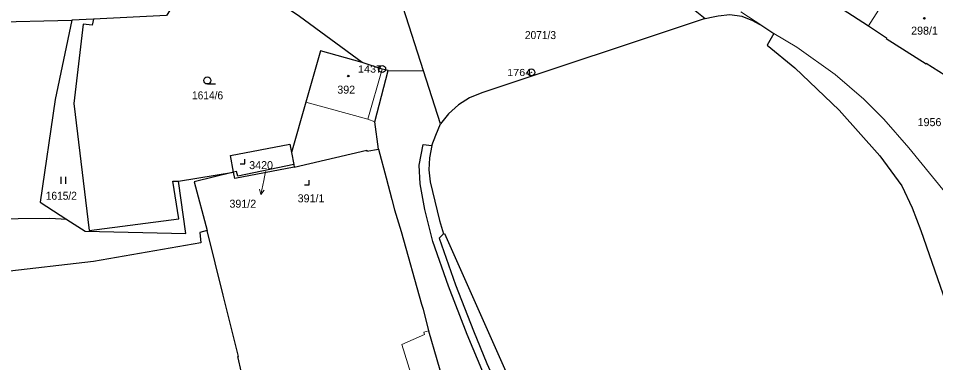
# Model space of a CAD drawing. Extents: x -679733 to -673243, y -1075091 to -1066557.
# Drawn here: x -676852.3 to -676657.5, y -1071521.5 to -1071448.4 of the extents above; entities that cross this region are included whole.
import ezdxf
from ezdxf.enums import TextEntityAlignment as Align

# ---------------------------------------------------------------- set-up
doc = ezdxf.new("R2010")
doc.units = 0
doc.header["$LTSCALE"] = 0.68
for name, color, linetype, lineweight in [('1', 7, 'Continuous', 25), ('3', 7, 'Continuous', 25), ('4', 7, 'Continuous', 13), ('5', 7, 'Continuous', 25), ('7', 7, 'Continuous', 13), ('8', 7, 'Continuous', 25)]:
    doc.layers.add(name, color=color, linetype=linetype, lineweight=lineweight)
doc.layers.add('2', color=7, linetype='Continuous')

msp = doc.modelspace()

# ---------------------------------------------------------------- linework, layer by layer
at = {"layer": '1'}
for p, q in [((-676836.4, -1071448.49), (-676841, -1071448.71)), ((-676773.77, -1071459.42), (-676766.29, -1071459.51))]:
    msp.add_line(p, q, dxfattribs=at)
for points in [[(-676708.35, -1071426.89), (-676710.19, -1071425.7), (-676715.7, -1071440.94), (-676706.46, -1071448.39)], [(-676813.29, -1071435.89), (-676820.87, -1071447.75), (-676836.4, -1071448.49)], [(-676779.29, -1071457.75), (-676792.63, -1071447.96), (-676797.15, -1071444.93), (-676806.53, -1071439.04), (-676813.29, -1071435.89)], [(-676683.31, -1071443.03), (-676678.47, -1071446), (-676678.32, -1071445.78), (-676677.41, -1071446.35), (-676671.78, -1071449.97), (-676667.98, -1071452.47), (-676668.07, -1071452.62), (-676659.58, -1071457.99), (-676659.52, -1071457.9), (-676655.53, -1071460.4), (-676642.15, -1071468.89)], [(-676766.29, -1071459.51), (-676770.64, -1071446.07), (-676770.3, -1071445.35)], [(-676957.85, -1071463.57), (-676942.22, -1071453.22), (-676935.48, -1071451.38), (-676927.1, -1071450.58), (-676915.56, -1071448.55), (-676905.18, -1071446.9), (-676895.66, -1071447), (-676891.77, -1071447.7), (-676885.75, -1071448.33), (-676876.83, -1071449.08), (-676869.56, -1071449.42), (-676858.82, -1071449.13), (-676841, -1071448.71)], [(-676706.46, -1071448.39), (-676704.76, -1071448.03), (-676703.73, -1071447.81), (-676701.26, -1071447.54), (-676698.72, -1071447.92), (-676696.46, -1071448.78), (-676694.26, -1071449.98), (-676691.89, -1071451.57), (-676693.28, -1071454.07), (-676687.45, -1071458.85), (-676678.05, -1071467.82), (-676669.42, -1071477.57), (-676664.74, -1071483.89), (-676662.51, -1071488.58), (-676660.71, -1071493.4), (-676651.25, -1071520.53)], [(-676841, -1071448.71), (-676844.52, -1071465.57), (-676847.69, -1071487.35), (-676842.01, -1071491.03)], [(-676836.4, -1071448.49), (-676836.62, -1071449.77), (-676838.6, -1071449.62), (-676840.54, -1071466.42), (-676837.3, -1071493.41), (-676818.28, -1071490.9), (-676819.52, -1071482.92), (-676818.29, -1071482.89), (-676806.65, -1071481)], [(-676706.46, -1071448.39), (-676753.93, -1071464.16), (-676756.51, -1071465.26), (-676758.86, -1071466.72), (-676760.97, -1071468.64), (-676762.66, -1071470.73)], [(-676779.29, -1071457.75), (-676788.15, -1071455.25), (-676791.29, -1071466.12), (-676794.31, -1071476.87), (-676793.84, -1071479.38), (-676793.73, -1071479.96)], [(-676773.77, -1071459.42), (-676775.08, -1071459.11), (-676779.29, -1071457.75)], [(-676775.85, -1071476.13), (-676776.64, -1071470.3), (-676773.77, -1071459.42)], [(-676764.54, -1071475.38), (-676763.69, -1071473.15), (-676762.66, -1071470.73), (-676766.29, -1071459.51)], [(-676806.65, -1071481), (-676807.31, -1071477.46), (-676794.65, -1071475.1), (-676794.31, -1071476.87)], [(-676753.54, -1071523.73), (-676757.03, -1071515.47), (-676760.96, -1071505.19), (-676764.28, -1071495.76), (-676766.04, -1071488.95), (-676767.03, -1071483.49), (-676767.2, -1071479.54), (-676766.39, -1071475.11), (-676764.54, -1071475.38)], [(-676793.73, -1071479.96), (-676778.34, -1071476.35), (-676778.3, -1071476.55), (-676775.85, -1071476.13)], [(-676775.85, -1071476.13), (-676774.25, -1071482.22), (-676773, -1071486.82), (-676772.46, -1071488.98), (-676771.07, -1071493.58), (-676766.7, -1071509.07), (-676766.37, -1071510.09), (-676765.26, -1071514.71), (-676761.72, -1071526.9), (-676760.25, -1071531.41), (-676759.56, -1071533.91), (-676756.1, -1071546.01)], [(-676764.54, -1071475.38), (-676765.03, -1071477.96), (-676765.17, -1071480.52), (-676764.91, -1071483.06), (-676762.89, -1071491.26), (-676762.03, -1071494.13)], [(-676806.65, -1071481), (-676815.01, -1071483.07), (-676812.2, -1071493.43)], [(-676793.84, -1071479.38), (-676805.72, -1071481.85), (-676805.99, -1071480.9), (-676806.65, -1071481)], [(-676793.73, -1071479.96), (-676806.39, -1071482.37), (-676806.65, -1071481)], [(-676842.01, -1071491.03), (-676838.11, -1071493.55), (-676816.77, -1071494.03), (-676818.29, -1071482.89)], [(-676842.01, -1071491.03), (-676845.64, -1071490.85), (-676865.79, -1071491.03), (-676869.03, -1071491.11), (-676888.24, -1071491.34), (-676898.16, -1071492.99), (-676910.53, -1071491.92), (-676915.98, -1071492.56), (-676921.53, -1071495.81), (-676926.39, -1071499.92), (-676929.35, -1071501.56), (-676945.58, -1071505.99), (-676961.23, -1071514.08), (-676969.66, -1071515.7), (-676981.66, -1071516.36), (-676989.83, -1071513.04), (-676992.52, -1071510.05), (-676993.5, -1071508.1), (-676992.89, -1071505.67), (-676991.53, -1071503.51), (-676987.74, -1071501.24), (-676980.5, -1071498.63), (-676974.34, -1071494.41)], [(-676812.2, -1071493.43), (-676813.76, -1071493.82), (-676813.57, -1071496.03), (-676836.38, -1071500.01), (-676855.98, -1071502.22), (-676871.03, -1071503.58), (-676888.75, -1071507.78), (-676905.07, -1071511.48), (-676917.72, -1071513.49), (-676933.11, -1071515.38), (-676941.77, -1071519.32), (-676931.84, -1071554.09), (-676916.35, -1071551.78)], [(-676804.95, -1071523.55), (-676805.72, -1071520.17), (-676805.55, -1071520.12), (-676808.81, -1071507.1), (-676812.2, -1071493.43)], [(-676762.03, -1071494.13), (-676762.94, -1071495.05), (-676759.5, -1071504.94), (-676755.7, -1071514.74), (-676752.84, -1071521.62), (-676750.39, -1071527.09), (-676748.58, -1071527.96), (-676747.78, -1071528.25), (-676742.3, -1071540.02), (-676742.65, -1071540.18), (-676742.64, -1071543.96), (-676732.93, -1071565.35), (-676728.85, -1071575.59), (-676726.29, -1071582.59), (-676724.59, -1071589.37), (-676723.72, -1071596.33), (-676723.48, -1071603.98), (-676723.51, -1071620.81), (-676724.06, -1071638.73), (-676724.85, -1071648.2), (-676725.15, -1071652.2), (-676724.86, -1071656.66), (-676723.85, -1071663.89)], [(-676762.03, -1071494.13), (-676761.82, -1071494.06), (-676721.65, -1071584.53), (-676720.32, -1071587.99), (-676719.96, -1071590.96), (-676720.27, -1071640.98), (-676720.61, -1071652.09)]]:
    msp.add_lwpolyline(points, dxfattribs=at)
at = {"layer": '3'}
for p, q in [((-676812.193, -1071462.28), (-676810.443, -1071462.28)), ((-676843.251, -1071483.49), (-676843.251, -1071481.99)), ((-676842.25, -1071483.49), (-676842.25, -1071481.99))]:
    msp.add_line(p, q, dxfattribs=at)
for points in [[(-676805.221, -1071479.22), (-676804.22, -1071479.22), (-676804.22, -1071478.22)], [(-676791.581, -1071483.71), (-676790.58, -1071483.71), (-676790.58, -1071482.71)]]:
    msp.add_lwpolyline(points, dxfattribs=at)
msp.add_circle((-676812.1929, -1071461.5298), 0.75, dxfattribs=at)
at = {"layer": '4'}
for p, q in [((-676671.78, -1071449.97), (-676668.01, -1071443.94)), ((-676698.88, -1071446.98), (-676694.26, -1071449.98)), ((-676691.89, -1071451.57), (-676687.02, -1071454.49)), ((-676678.86, -1071460.29), (-676687.02, -1071454.49)), ((-676775.08, -1071459.11), (-676778.09, -1071469.74)), ((-676672.81, -1071465.49), (-676678.86, -1071460.29)), ((-676668.56, -1071469.74), (-676672.81, -1071465.49)), ((-676778.09, -1071469.74), (-676791.29, -1071466.12)), ((-676778.09, -1071469.74), (-676776.64, -1071470.3)), ((-676663.26, -1071475.84), (-676668.56, -1071469.74)), ((-676636.76, -1071508.39), (-676663.26, -1071475.84)), ((-676770.91, -1071517.6), (-676766.07, -1071515.51)), ((-676766.22, -1071514.99), (-676765.26, -1071514.71)), ((-676766.07, -1071515.51), (-676766.22, -1071514.99)), ((-676766.03, -1071532.96), (-676770.91, -1071517.6))]:
    msp.add_line(p, q, dxfattribs=at)
at = {"layer": '5'}
for centre in [(-676659.9268, -1071448.3392), (-676782.2568, -1071460.5992)]:
    msp.add_circle(centre, 0.175, dxfattribs=at)
at = {"layer": '7'}
msp.add_line((-676800.803, -1071485.736), (-676800.12, -1071484.848), dxfattribs=at)
msp.add_lwpolyline([(-676799.85, -1071480.88), (-676800.23, -1071482.79), (-676800.803, -1071485.736), (-676801.103, -1071484.657)], dxfattribs=at)
at = {"layer": '8'}
for centre, radius in [((-676775.08, -1071459.1098), 0.75), ((-676775.08, -1071459.1098), 0.03), ((-676743.4, -1071459.8298), 0.75), ((-676743.4, -1071459.8298), 0.03)]:
    msp.add_circle(centre, radius, dxfattribs=at)

# ---------------------------------------------------------------- texts
at = {"layer": '2', "width": 0.95}
for s, p in [('2071/3', (-676744.76, -1071452.749)), ('1614/6', (-676815.45, -1071465.55)), ('1615/2', (-676846.51, -1071486.87))]:
    msp.add_text(s, height=1.7, dxfattribs=at).set_placement(p)
at = {"layer": '2'}
for s, p in [('298/1', (-676662.74, -1071451.81)), ('392', (-676784.6, -1071464.34)), ('1956', (-676661.37, -1071471.239)), ('3420', (-676803.31, -1071480.37)), ('391/1', (-676793.02, -1071487.42))]:
    msp.add_text(s, height=1.7, dxfattribs=at).set_placement(p)
msp.add_text('391/2', height=1.7, dxfattribs=at).set_placement((-676801.819, -1071488.563), align=Align.RIGHT)
at = {"layer": '8', "width": 1.15}
for s, p in [('1437', (-676775.079, -1071459.86)), ('1764', (-676743.399, -1071460.58))]:
    msp.add_text(s, height=1.5, dxfattribs=at).set_placement(p, align=Align.RIGHT)

doc.saveas('drawing.dxf')
